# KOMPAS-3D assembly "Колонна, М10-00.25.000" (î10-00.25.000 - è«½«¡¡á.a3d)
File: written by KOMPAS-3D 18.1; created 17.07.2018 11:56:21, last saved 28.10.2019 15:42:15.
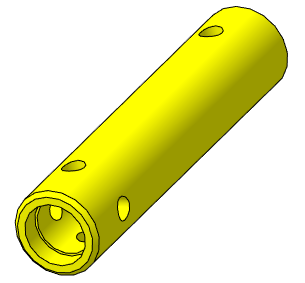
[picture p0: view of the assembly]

Document properties: Автор: Милов; Полное имя файла: D:\Magna\Магна Ins\Магна ins 10\М10-00.00.000\3Д\М10-00.25.000 - Колонна.a3d

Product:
- Part/product: Колонна  | designation М10-00.25.000  | pos. 0
    Материал: Полипропилен  ГОСТ 26996-86 (density 900 kg/m3)
    Масса: 1.63913
    Раздел спецификации: Сборочные единицы
    Форматы листов документа: A3
    source file: М10-00.25.000 - Колонна.cdw
  - Component [detail]: Отбойник  | designation М10-00.25.002  | pos. 0  | Раздел спецификации: Детали; Форматы листов документа: A4; source file: М10-00.25.002 - Отбойник.cdw, М10-00.25.002 - Отбойник.m3d
  - Component [detail]: Отбойник  | designation М5-00.11.002  | pos. 1  | Раздел спецификации: Детали; Форматы листов документа: A4; Примечание: Заим.; source file: ..\..\..\Магна ins 5\М5-00.00.000 - Насос Магна ins 5-C-N\3Д модель\М5-00.11.002 - Отбойник.m3d, ..\..\..\Магна ins 5\М5-00.00.000 - Насос Магна ins 5-C-N\Чертежи\М5-00.11.002 - Отбойник.cdw
  - Component [detail]: Колонна  | designation М10-00.25.001  | pos. 2  | Масса: 1.63913; Раздел спецификации: Детали; Форматы листов документа: A4; source file: М10-00.25.001 - Колонна.cdw, М10-00.25.001 - Колонна.m3d
- Part/product: Колонна ПВХ  | designation М13-01.25.000-1  | pos. 0
    Материал: Полипропилен  ГОСТ 26996-86 (density 900 kg/m3)
    Масса: 0.77209
    Раздел спецификации: Сборочные единицы
    Форматы листов документа: A3
  - Component [detail]: Колонна ПВХ  | designation М13-01.25.001  | pos. 2  | Масса: 0.781919; Раздел спецификации: Детали; Форматы листов документа: A4

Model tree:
1. Эскиз:1  (with: Операция вращения:1)
2. Вырезать элемент выдавливания:1  (with: Операция вращения:1, Элемент выдавливания:2)  (labels: Полипропилен  ГОСТ 26996-86; М10-00.25.002 - Отбойник.m3d; М10-00.25.001 - Колонна.m3d)
     Расстояние 1 = 17.5; Расстояние = -56
3. Фаска:3  (with: Операция вращения:1)  (labels: Полипропилен  ГОСТ 26996-86)
     Угол = 45; Длина 1 = 4; Длина 2 = 4; Расстояние = -46

Referenced files in D:\Magna\Магна Ins\Магна ins 10\М10-00.00.000\3Д\: М10-00.25.001 - Колонна.m3d, М10-00.25.001 - Колонна.cdw, М10-00.25.002 - Отбойник.m3d, М10-00.25.002 - Отбойник.cdw, М10-00.25.000 - Колонна.cdw
Referenced files in D:\Magna\Магна Ins\Магна ins 5\М5-00.00.000 - Насос Магна ins 5-C-N\3Д модель\: М5-00.11.002 - Отбойник.m3d
Referenced files in D:\Magna\Магна Ins\Магна ins 5\М5-00.00.000 - Насос Магна ins 5-C-N\Чертежи\: М5-00.11.002 - Отбойник.cdw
